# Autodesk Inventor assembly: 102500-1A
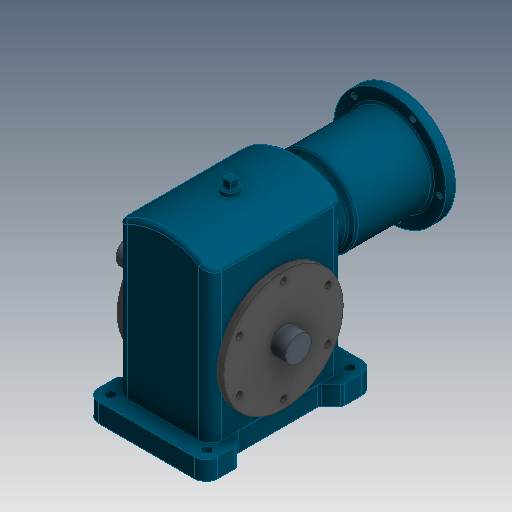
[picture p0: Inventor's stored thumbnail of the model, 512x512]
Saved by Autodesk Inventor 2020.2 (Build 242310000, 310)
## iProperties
Created: 2000-10
Part Number: 102500-1A
Document SubType Name: Assembly
Designer: wymerj
Mass: 19938 g
Surface Area: 7536.59 cm^2
Volume: 3591.38 cm^3
Density: 5.55163 g/cm^3
Control State: 0
Master: False
Checked Out: False
Shininess: 0.0
Length Units: 11269
Angle Units: 11279
Time Units: 11290
Mass Units: 11283
Length Display Precision: 3
Angle Display Precision: 2
Compacted: True
Dimensions: 291,8x377x254 mm
Mass: 19,938 kg
DocNumber: 102500-1B.iam
Folder: 01 - Themengebiete\Simplification\01 - Packaging machine\
VDS_Category: 3D Komponenten
VDS_NumSchm: Kein
Density: 0.0
Volumn: 0.0
Area: 0.0
PropertySet Name: Model Information
Author: wymerj
Revision Number: -
Title: 102500-1A
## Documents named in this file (10)
- D:\07 - DEMODATEN\OTX 2019 - Dataset - UPDATE - Dez2019\Designs\07-Packing machine\102500-1A.iam
- D:\07 - DEMODATEN\OTX 2019 - Dataset - UPDATE - Dez2019\Designs\07-Packing machine\Parts\ADSK-011841.ipt
- D:\07 - DEMODATEN\OTX 2019 - Dataset - UPDATE - Dez2019\Designs\07-Packing machine\Parts\ADSK-011827.ipt
- D:\07 - DEMODATEN\OTX 2019 - Dataset - UPDATE - Dez2019\Designs\07-Packing machine\Parts\ADSK-011237.ipt
- D:\07 - DEMODATEN\OTX 2019 - Dataset - UPDATE - Dez2019\Designs\07-Packing machine\Parts\ADSK-011238.ipt
- D:\07 - DEMODATEN\OTX 2019 - Dataset - UPDATE - Dez2019\Designs\07-Packing machine\Parts\ADSK-011241.ipt
- D:\07 - DEMODATEN\OTX 2019 - Dataset - UPDATE - Dez2019\Designs\07-Packing machine\Parts\ADSK-011710.ipt
- D:\07 - DEMODATEN\OTX 2019 - Dataset - UPDATE - Dez2019\Designs\07-Packing machine\Parts\ADSK-011240.ipt
- D:\07 - DEMODATEN\OTX 2019 - Dataset - UPDATE - Dez2019\Designs\07-Packing machine\Parts\ADSK-011242.ipt
- D:\07 - DEMODATEN\OTX 2019 - Dataset - UPDATE - Dez2019\Designs\07-Packing machine\Parts\ADSK-011243.ipt
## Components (10 placed, 9 different names)
1. ADSK-011827:1 — Flush:7, Flush:1, Mate:1, Mate:2, Mate:5, Angle:1, Mate:6, Flush:3, Insert:1, Angle:2
2. ADSK-011841:1 — Flush:7, Flush:1, Mate:1, Mate:3, Mate:4, Flush:9, Passend:14
3. ADSK-011841:2 — Mate:2, Mate:3, Mate:4, Mate:8
4. ADSK-011237:1 — Mate:5, Angle:1, Mate:6, Rotation:1, Mate:9, Mate:10, Mate:13
5. ADSK-011238:1 — Flush:2, Rotation:1, Rotation:2, Insert:1
6. ADSK-011240:2 — Flush:2, Rotation:2, Mate:8, Flush:5
7. ADSK-011241:1 — Flush:3, Mate:12, Flush:5, Passend:14
8. ADSK-011242:1 — Flush:8, Mate:9, Mate:10, Flush:4, Mate:11, Mate:13, Flush:6
9. ADSK-011243:1 — Flush:8, Flush:4, Mate:11, Flush:6, Angle:2
10. ADSK-011710:1 — Flush:9, Mate:12
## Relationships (27: Mate 13, Flush 9, Angle 2, RelateRotation 2, Insert 1)
- Flush:7: ADSK-011827:1 ↔ ADSK-011841:1
- Flush:1: ADSK-011827:1 ↔ ADSK-011841:1
- Mate:1: ADSK-011827:1 ↔ ADSK-011841:1
- Mate:2: ADSK-011827:1 ↔ ADSK-011841:2
- Mate:3: ADSK-011841:1 ↔ ADSK-011841:2
- Mate:4: ADSK-011841:1 ↔ ADSK-011841:2
- Mate:5: ADSK-011827:1 ↔ ADSK-011237:1
- Angle:1: ADSK-011827:1 ↔ ADSK-011237:1
- Mate:6: ADSK-011827:1 ↔ ADSK-011237:1
- Flush:2: ADSK-011238:1 ↔ ADSK-011240:2
- Rotation:1 [RelateRotation]: ADSK-011237:1 ↔ ADSK-011238:1
- Rotation:2 [RelateRotation]: ADSK-011238:1 ↔ ADSK-011240:2
- Flush:3: ADSK-011827:1 ↔ ADSK-011241:1
- Mate:8: ADSK-011841:2 ↔ ADSK-011240:2
- Flush:8: ADSK-011242:1 ↔ ADSK-011243:1
- Mate:9: ADSK-011237:1 ↔ ADSK-011242:1
- Mate:10: ADSK-011237:1 ↔ ADSK-011242:1
- Flush:4: ADSK-011242:1 ↔ ADSK-011243:1
- Mate:11: ADSK-011242:1 ↔ ADSK-011243:1
- Flush:9: ADSK-011841:1 ↔ ADSK-011710:1
- Mate:12: ADSK-011241:1 ↔ ADSK-011710:1
- Flush:5: ADSK-011240:2 ↔ ADSK-011241:1
- Insert:1: ADSK-011827:1 ↔ ADSK-011238:1
- Mate:13: ADSK-011237:1 ↔ ADSK-011242:1
- Flush:6: ADSK-011242:1 ↔ ADSK-011243:1
- Angle:2: ADSK-011827:1 ↔ ADSK-011243:1
- Passend:14 [Mate]: ADSK-011841:1 ↔ ADSK-011241:1
